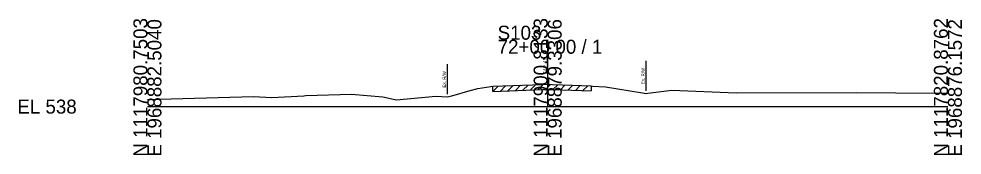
# Model space of a CAD drawing. Extents: x -26 to 163, y -10 to 24018.
# Drawn here: x -25.7 to 162.8, y 19990.3 to 20017.5 of the extents above; entities that cross this region are included whole.
import ezdxf

# ---------------------------------------------------------------- set-up
doc = ezdxf.new("R2010")
doc.units = 0
for name, color, linetype in [('RD_GPK_XS_Cell', 7, 'Continuous'), ('RD_XS_ExGround', 7, 'Continuous'), ('RD_XS_ExPaveRet', 7, 'Continuous'), ('RD_XS_ExRW', 7, 'Continuous'), ('RD_XS_TX_Elev_EX', 7, 'Continuous')]:
    doc.layers.add(name, color=color, linetype=linetype)

msp = doc.modelspace()

# ---------------------------------------------------------------- linework, layer by layer
at = {"layer": 'RD_GPK_XS_Cell'}
for p, q in [((80, 20000), (80, 20013.36)), ((0, 20000), (80, 20000)), ((80, 20000), (160, 20000))]:
    msp.add_line(p, q, dxfattribs=at)
at = {"layer": 'RD_XS_ExGround'}
msp.add_lwpolyline([(0, 20001.44), (21.21, 20002.03), (24.86, 20001.84), (31.25, 20002.17), (31.64, 20002.19), (40.81, 20002.5), (47.07, 20001.92), (49.76, 20001.37), (57.64, 20002.1), (59.9, 20001.96), (60.82, 20002.17), (64.54, 20003.2), (66.07, 20003.62), (68.61, 20003.99), (69.04, 20004.05), (78.98, 20004.41), (80.11, 20004.45), (80.97, 20004.42), (88.68, 20004.12), (88.98, 20004.11), (91.57, 20003.95), (98.95, 20002.75), (99.63, 20002.63), (100.04, 20002.69), (104.84, 20003.3), (117.69, 20002.78), (141.63, 20002.83), (149.6, 20002.73), (160, 20002.69)], dxfattribs=at)
at = {"layer": 'RD_XS_ExPaveRet'}
for p, q in [((69.04, 20003.05), (70.08, 20004.08)), ((69.04, 20003.05), (69.04, 20004.05)), ((69.04, 20003.05), (78.98, 20003.41)), ((70.54, 20003.1), (71.58, 20004.14)), ((72.04, 20003.16), (73.08, 20004.2)), ((73.54, 20003.21), (74.58, 20004.25)), ((75.04, 20003.27), (76.08, 20004.31)), ((76.54, 20003.32), (77.58, 20004.36)), ((78.04, 20003.38), (79.08, 20004.42)), ((78.98, 20003.41), (80.11, 20003.45)), ((79.54, 20003.43), (80.54, 20004.44)), ((80.11, 20003.45), (80.97, 20003.42)), ((80.97, 20003.42), (88.68, 20003.12)), ((81.04, 20003.42), (82, 20004.38)), ((82.54, 20003.36), (83.5, 20004.32)), ((84.04, 20003.3), (85, 20004.27)), ((85.54, 20003.24), (86.5, 20004.21)), ((87.04, 20003.19), (88, 20004.15)), ((88.68, 20004.12), (88.68, 20003.12))]:
    msp.add_line(p, q, dxfattribs=at)
at = {"layer": 'RD_XS_ExRW'}
for p, q in [((99.63, 20009.13), (99.63, 20003.13)), ((59.9, 20008.46), (59.9, 20002.46))]:
    msp.add_line(p, q, dxfattribs=at)

# ---------------------------------------------------------------- texts
at = {"layer": 'RD_GPK_XS_Cell'}
for s, p in [('N 1117980.7503', (0, 19990)), ('E 1968882.5040', (2.8, 19990)), ('N 1117900.8133', (80, 19990)), ('E 1968879.3306', (82.8, 19990)), ('N 1117820.8762', (160, 19990)), ('E 1968876.1572', (162.8, 19990))]:
    msp.add_text(s, height=2.8, rotation=90, dxfattribs=at).set_placement(p)
for s, p in [('S103', (70, 20013.36)), ('72+00.00 / 1', (70, 20010.56)), ('EL 538', (-26, 19998.6))]:
    msp.add_text(s, height=2.8, dxfattribs=at).set_placement(p)
at = {"layer": 'RD_XS_ExRW'}
for p in [(99.38, 20004.48), (59.65, 20003.8)]:
    msp.add_text('Ex. R/W ', height=0.65, rotation=90, dxfattribs=at).set_placement(p)
at = {"layer": 'RD_XS_TX_Elev_EX'}
msp.add_text('542.45', height=0.8, rotation=90, dxfattribs=at).set_placement((79.9, 20006.45))

doc.saveas('drawing.dxf')
